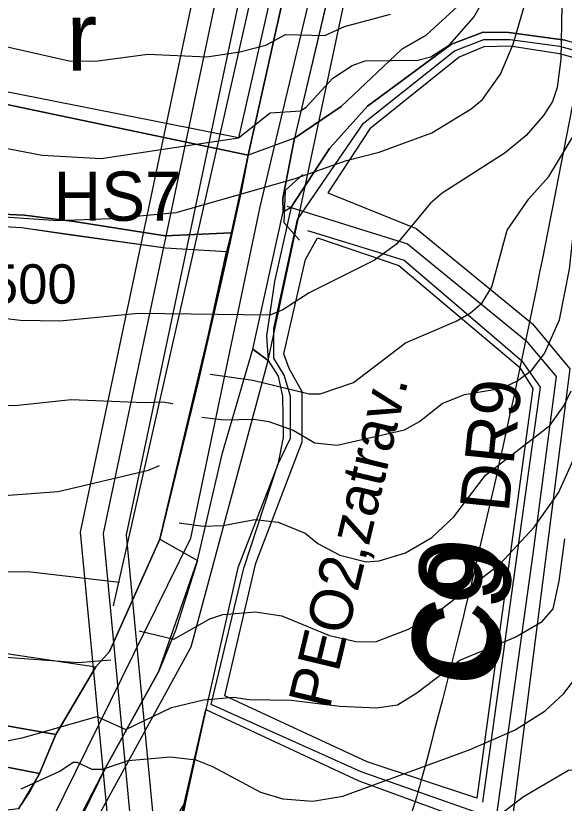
# Model space of a CAD drawing. Extents: x -684583 to -680383, y -1157874 to -1154904.
# Drawn here: x -683047.3 to -682880.2, y -1156898.5 to -1156658.6 of the extents above; entities that cross this region are included whole.
import ezdxf

# ---------------------------------------------------------------- set-up
doc = ezdxf.new("R2010")
doc.units = 0
for name, color, linetype in [('01_DOPRAVA', 7, 'Continuous'), ('01_OBVOD PÚ', 7, 'Continuous'), ('01_VRSTEVNICE', 7, 'Continuous'), ('02_KULTURY NÁVRH', 7, 'Continuous'), ('02_KULTURY STAV', 7, 'Continuous'), ('03_PC_NÁVRH', 7, 'Continuous'), ('03_PC_OBJEKTY_NÁVRH', 7, 'Continuous'), ('03_PC_OBJEKTY_STAV', 7, 'Continuous'), ('03_PC_POPIS_NÁVRH', 7, 'Continuous'), ('04_ZPF_OP_ORGAN', 7, 'Continuous'), ('06_BIOGEOGRAFIE', 7, 'Continuous'), ('06_ÚSES_IP', 7, 'Continuous'), ('07_ELEKTRO', 7, 'Continuous'), ('07_OCH_P A POPISY TI', 7, 'Continuous'), ('Implicitní', 7, 'Continuous')]:
    doc.layers.add(name, color=color, linetype=linetype)

msp = doc.modelspace()

# ---------------------------------------------------------------- linework, layer by layer
at = {"layer": '01_DOPRAVA'}
msp.add_lwpolyline([(-683054.51, -1157758.92), (-683045.66, -1157702.14), (-683033.32, -1157625.99), (-683033.32, -1157571.3), (-683045.07, -1157508.09), (-683105.62, -1157372.25), (-683148.82, -1157294.04), (-683163.81, -1157254.05), (-683168.81, -1157196.71), (-683165.28, -1157159.67), (-683135.89, -1157075.28), (-683079.46, -1156981.49), (-683035.96, -1156902.98), (-682993.94, -1156817.72), (-682972.78, -1156716.87), (-682952.5, -1156631.31), (-682921.05, -1156497.23), (-682883.43, -1156372.57), (-682870.79, -1156344.34), (-682802.61, -1156200.56), (-682782.62, -1156147.93)], dxfattribs=at)
at = {"layer": '01_OBVOD PÚ'}
for points in [[(-683140.88, -1156658.35), (-683073.72, -1156680.66), (-682976.5, -1156701.12), (-682978.52, -1156711.74), (-682983.61, -1156734.83), (-682991.74, -1156770.13), (-683003.34, -1156818.01)], [(-682976.5, -1156701.12), (-683073.72, -1156680.66), (-683140.88, -1156658.35)], [(-683046.43, -1156900.19), (-683042.88, -1156894.65), (-683040.05, -1156889.46), (-683036.16, -1156880.14), (-683035.02, -1156877.58), (-683022.83, -1156856.96), (-683018.7, -1156852.25), (-683003.34, -1156818.01), (-682983.61, -1156734.83), (-682976.5, -1156701.12)], [(-683003.34, -1156818.01), (-683018.7, -1156852.25), (-683022.83, -1156856.96), (-683035.02, -1156877.58), (-683036.16, -1156880.14), (-683040.05, -1156889.46), (-683042.88, -1156894.65), (-683045.48, -1156898.75)]]:
    msp.add_lwpolyline(points, dxfattribs=at)
for points in [[(-682989.36, -1156869.91), (-682942.73, -1156891.65), (-682905.01, -1156905.43), (-682910.21, -1156938.74), (-682911.04, -1156940.97), (-682922.78, -1156975.26), (-682939.17, -1157002.56), (-682940.26, -1157005.08), (-682945.41, -1157016.69), (-682955.51, -1157012.45), (-682965.71, -1157007.37), (-682974.58, -1157002.46), (-682979.82, -1156999.75), (-683040.73, -1156970.35), (-683038.56, -1156961.55), (-683037.65, -1156957.9), (-683028.68, -1156946.32), (-683018.91, -1156933.75), (-683016.64, -1156930.91), (-682996.6, -1156901.27), (-682995.5, -1156898)], [(-682989.36, -1156869.91), (-682942.73, -1156891.65), (-682905.01, -1156905.43), (-682910.21, -1156938.74), (-682922.78, -1156975.26), (-682939.17, -1157002.56), (-682945.41, -1157016.69), (-682955.51, -1157012.45), (-682965.71, -1157007.37), (-682974.58, -1157002.46), (-682979.82, -1156999.75), (-683040.73, -1156970.35), (-683037.34, -1156957.14), (-683028.68, -1156946.32), (-683018.91, -1156933.75), (-683016.64, -1156930.91), (-683005.44, -1156914.73), (-682996.6, -1156901.27)]]:
    msp.add_lwpolyline(points, close=True, dxfattribs=at)
at = {"layer": '01_VRSTEVNICE'}
for points in [[(-683179.87, -1156698.71), (-683173.88, -1156700.28), (-683165.89, -1156700.42), (-683139.93, -1156697.29), (-683127.95, -1156697.57), (-683113.97, -1156700.28), (-683097.99, -1156706.41), (-683087.15, -1156712.12), (-683076.31, -1156716.54), (-683058.34, -1156719.4), (-683034.37, -1156720.96), (-683018.4, -1156720.39), (-682998.42, -1156718.54), (-682962.48, -1156708.27), (-682946.5, -1156702.71), (-682936.52, -1156700.14), (-682920.54, -1156694.29), (-682908.56, -1156687.02), (-682905.13, -1156684.16), (-682899.57, -1156676.46), (-682895.72, -1156667.33), (-682888.45, -1156642.22)], [(-683174.02, -1156658.34), (-683167.6, -1156662.48), (-683153.34, -1156668.04), (-683141.35, -1156670.9), (-683125.38, -1156673.32), (-683111.4, -1156676.6), (-683096.85, -1156681.45), (-683080.59, -1156689.44), (-683062.04, -1156696.71), (-683039.22, -1156701.14), (-683021.25, -1156702.14), (-682979.45, -1156695.86), (-682969.75, -1156688.16), (-682960.48, -1156687.59), (-682958.77, -1156686.45), (-682950.64, -1156677.6), (-682944.79, -1156673.75), (-682940.8, -1156672.32), (-682924.82, -1156672.18), (-682920.83, -1156671.18), (-682915.12, -1156667.47), (-682907.7, -1156659.06), (-682901.28, -1156647.65)], [(-682990.58, -1156780.88), (-682983.88, -1156781.73), (-682974.75, -1156781.45), (-682970.18, -1156782.16), (-682962.76, -1156784.87), (-682956.2, -1156788.72), (-682949.36, -1156789.43), (-682928.82, -1156784.73), (-682924.25, -1156782.16), (-682917.4, -1156776.74), (-682910.56, -1156774.03), (-682899.15, -1156772.03), (-682894.58, -1156769.89), (-682890.01, -1156766.61), (-682886.16, -1156761.48), (-682881.6, -1156751.21), (-682878.6, -1156735.8), (-682877.46, -1156725.53), (-682875.47, -1156717.83), (-682866.05, -1156697.29), (-682855.92, -1156681.88), (-682849.93, -1156669.04), (-682844.51, -1156648.36)], [(-682988.01, -1156767.75), (-682975.03, -1156769.61), (-682957.91, -1156773.74), (-682954.49, -1156773.74), (-682944.36, -1156770.32), (-682928.53, -1156758.2), (-682913.12, -1156751.63), (-682908.7, -1156749.07), (-682905.14, -1156746.07), (-682902.28, -1156741.22), (-682897.58, -1156723.96), (-682891.01, -1156714.4), (-682884.88, -1156707.56), (-682874.04, -1156689.58), (-682869.33, -1156678.17), (-682865.62, -1156660.2), (-682859.2, -1156647.36)], [(-682880.89, -1156655.63), (-682881.17, -1156671.89), (-682882.31, -1156680.45), (-682883.74, -1156684.73), (-682886.45, -1156689.01), (-682891.73, -1156695.15), (-682898.15, -1156700.42), (-682917.4, -1156712.69), (-682920.97, -1156715.69), (-682931.24, -1156728.24), (-682937.94, -1156733.09), (-682957.91, -1156743.07), (-682965.9, -1156748.21), (-682969.9, -1156749.78), (-683009.84, -1156749.35), (-683033.8, -1156751.63), (-683045.78, -1156751.49), (-683053.77, -1156750.49)], [(-683123.1, -1156656.78), (-683109.12, -1156660.77), (-683101.13, -1156661.91), (-683083.16, -1156666.19), (-683078.88, -1156666.62), (-683072.88, -1156665.76), (-683058.91, -1156666.05), (-683030.95, -1156672.32), (-683022.96, -1156672.47), (-683006.98, -1156670.33), (-682989.01, -1156671.18), (-682979.03, -1156669.61), (-682971.04, -1156667.62), (-682965.05, -1156664.33), (-682953.06, -1156664.62), (-682947.07, -1156661.91), (-682933.09, -1156658.2)], [(-683183.58, -1156766.33), (-683154.76, -1156754.49), (-683150.48, -1156753.49), (-683141.92, -1156753.2), (-683117.67, -1156756.63), (-683104.84, -1156755.77), (-683096.28, -1156756.48), (-683087.72, -1156759.19), (-683082.73, -1156762.05), (-683066.89, -1156776.17), (-683061.19, -1156777.17), (-683047.49, -1156777.31), (-683030.38, -1156775.46), (-683008.12, -1156776.45), (-683002.42, -1156776.17), (-682999.42, -1156776.74)], [(-682997.43, -1156813.11), (-682990.15, -1156814.11), (-682984.16, -1156813.83), (-682974.43, -1156812.05), (-682967.33, -1156812.83), (-682959.05, -1156816.25), (-682955.2, -1156819.39), (-682948.5, -1156822.96), (-682940.51, -1156824.95), (-682936.52, -1156824.67), (-682928.53, -1156822.24), (-682920.54, -1156817.53), (-682913.84, -1156811.26), (-682904.14, -1156798.56), (-682884.59, -1156783.44), (-682880.32, -1156777.45), (-682878.03, -1156772.89)], [(-683009.69, -1156845.92), (-682999.14, -1156848.49), (-682988.11, -1156842.32), (-682984.2, -1156840.99), (-682974.18, -1156840.21), (-682966.19, -1156841.36), (-682951.64, -1156847.35), (-682943.65, -1156849.2), (-682937.66, -1156849.34), (-682927.67, -1156845.49), (-682919.97, -1156841.21), (-682899.71, -1156825.52), (-682889.3, -1156814.4), (-682881.88, -1156803.98), (-682870.62, -1156778.88)], [(-683181.86, -1156796.14), (-683150.48, -1156794.43), (-683134.79, -1156791.29), (-683117.67, -1156785.58), (-683110.54, -1156784.87), (-683103.41, -1156785.72), (-683099.13, -1156787.29), (-683093.43, -1156790.72), (-683084.3, -1156798.85), (-683078.59, -1156802.13), (-683064.33, -1156804.27), (-683052.34, -1156804.84), (-683034.37, -1156803.56), (-683006.84, -1156796.99), (-683003.42, -1156795.57)], [(-683187.57, -1156813.11), (-683149.63, -1156810.69), (-683131.65, -1156808.26), (-683115.68, -1156805.27), (-683107.55, -1156805.84), (-683102.55, -1156809.69), (-683089.43, -1156824.95), (-683086.86, -1156826.24), (-683078.59, -1156827.66), (-683042.65, -1156827.95), (-683015.68, -1156831.09)], [(-683057.76, -1156881.01), (-683044.93, -1156878.44), (-683022.53, -1156872.03), (-683013.69, -1156876.02), (-682999.85, -1156869.31), (-682990.08, -1156866.95), (-682980.82, -1156866.12), (-682976.17, -1156866.89), (-682963.33, -1156867.03), (-682948.5, -1156868.89), (-682937.37, -1156869.46), (-682930.95, -1156868.46), (-682925.11, -1156864.89), (-682911.98, -1156854.91), (-682895.15, -1156847.92), (-682886.88, -1156843.07), (-682883.6, -1156839.22), (-682881.74, -1156830.8), (-682880.03, -1156817.96)], [(-683257.75, -1156901.55), (-683256.33, -1156895.56), (-683255.9, -1156887.86), (-683257.32, -1156875.88), (-683256.61, -1156867.32), (-683253.9, -1156860.76), (-683249.05, -1156856.05), (-683242.63, -1156852.77), (-683222.09, -1156847.21), (-683209.11, -1156841.07), (-683199.84, -1156834.94), (-683191.28, -1156831.51), (-683186.14, -1156830.51), (-683175.87, -1156830.23), (-683151.34, -1156832.37), (-683124.24, -1156832.94), (-683119.96, -1156833.8), (-683112.83, -1156837.08), (-683097.13, -1156847.35), (-683076.31, -1156851.2), (-683055.77, -1156853.62), (-683028.24, -1156855.62), (-683018.25, -1156854.76)], [(-683045.64, -1156894.13), (-683033.8, -1156888.71), (-683029.81, -1156886), (-683028.67, -1156886), (-683024.1, -1156888.14), (-683020.68, -1156888.14), (-683012.97, -1156885.43), (-683000.14, -1156884.29), (-682992.43, -1156885.29), (-682987.3, -1156887.29), (-682972.75, -1156895.13), (-682965.9, -1156897.13), (-682956.77, -1156897.84), (-682947.64, -1156896.27), (-682908.84, -1156882.15), (-682895.15, -1156876.16), (-682886.02, -1156870.31), (-682880.32, -1156865.03), (-682871.76, -1156853.91)], [(-682910.56, -1156910.25), (-682892.58, -1156896.42), (-682878.89, -1156888.43), (-682873.75, -1156887.86), (-682870.47, -1156888.57), (-682868.62, -1156890.14), (-682866.62, -1156893.42), (-682865.91, -1156914.39)]]:
    msp.add_lwpolyline(points, dxfattribs=at)
at = {"layer": '02_KULTURY NÁVRH'}
msp.add_lwpolyline([(-682903.62, -1156902.45), (-682942.04, -1156888.88), (-682987.69, -1156868.38), (-682977.74, -1156826.92), (-682967.42, -1156795.29), (-682963.58, -1156787.26), (-682963.58, -1156774.45), (-682965.47, -1156768.08), (-682968.63, -1156762.95), (-682968.63, -1156753.87), (-682961.47, -1156720.7), (-682941.28, -1156691.3), (-682913.56, -1156669.28), (-682904.67, -1156665.82), (-682896.69, -1156665.82), (-682881.62, -1156667.93), (-682853.45, -1156675.62)], dxfattribs=at)
at = {"layer": '02_KULTURY STAV'}
for points in [[(-682976.5, -1156701.12), (-682962.69, -1156639.04), (-682954.15, -1156604.14), (-682942.64, -1156554.75), (-682933.67, -1156512.75), (-682930.39, -1156499.36), (-682924.11, -1156479.25), (-682902.2, -1156412.07), (-682889.47, -1156417.03), (-682900.44, -1156450.21), (-682906.88, -1156472.32), (-682918.22, -1156504.6), (-682924.52, -1156529.58), (-682939.75, -1156599.76), (-682949.64, -1156642.25), (-682962.33, -1156695.9)], [(-683111.36, -1156596.26), (-683052.03, -1156611.32), (-683020.92, -1156619.13), (-682998.1, -1156623.73), (-682980.21, -1156628.28), (-682966.28, -1156635.31), (-682962.69, -1156639.04), (-682976.5, -1156701.12), (-683073.72, -1156680.66), (-683140.88, -1156658.35), (-683138.49, -1156642.27), (-683137.49, -1156635.26), (-683133.3, -1156627.22), (-683127.66, -1156620.6)], [(-683003.34, -1156818.01), (-682991.86, -1156824.56), (-682984.3, -1156791.71), (-682974.99, -1156760.13), (-682965.76, -1156718.39), (-682965.87, -1156714.19), (-682962.33, -1156695.9), (-682976.5, -1156701.12), (-682978.52, -1156711.74), (-682983.61, -1156734.83), (-682991.74, -1156770.13)], [(-682965.76, -1156718.39), (-682963.36, -1156716.94), (-682968.45, -1156739.58), (-682970.92, -1156756.16), (-682970.35, -1156763.63), (-682974.99, -1156760.13)], [(-682983.03, -1156730.55), (-683001.65, -1156729.38), (-683030.45, -1156725.41), (-683045.5, -1156723.26), (-683057.74, -1156722.51), (-683065.56, -1156724.82), (-683070.42, -1156731.09), (-683078.9, -1156749.27), (-683089.07, -1156772.49), (-683108.63, -1156828.57), (-683108.54, -1156832.12), (-683084.67, -1156837.17), (-683086.85, -1156847.35), (-683022.84, -1156856.96), (-683018.7, -1156852.25), (-683003.34, -1156818.01), (-682991.74, -1156770.13)], [(-683056.67, -1156957.12), (-683048.23, -1156942.2), (-683019.85, -1156887.5), (-683003.71, -1156858.2), (-682991.86, -1156824.56), (-682984.3, -1156791.71), (-682974.99, -1156760.13), (-682970.35, -1156763.63), (-682967.31, -1156768.38), (-682966.01, -1156774.58), (-682965.79, -1156787.12), (-682967.42, -1156795.29), (-682979.58, -1156826.78), (-682989.36, -1156869.91), (-682995.5, -1156898), (-683016.64, -1156930.91), (-683028.68, -1156946.32), (-683037.65, -1156957.9), (-683040.73, -1156970.35)], [(-683086.85, -1156847.35), (-683022.84, -1156856.96), (-683035.02, -1156877.58), (-683070.73, -1156871.26), (-683070.45, -1156868.67), (-683069.49, -1156867.95), (-683068.52, -1156860.66), (-683079.75, -1156859.2)], [(-683131.89, -1156865.91), (-683104.59, -1156867.71), (-683070.73, -1156871.26), (-683035.02, -1156877.58), (-683040.05, -1156889.46), (-683070.37, -1156883.48), (-683118.26, -1156879.9), (-683137.12, -1156878.66), (-683137, -1156877.03)], [(-683118.26, -1156879.9), (-683070.37, -1156883.48), (-683040.05, -1156889.46), (-683046.43, -1156900.19), (-683055.25, -1156901.19), (-683100.37, -1156901.23), (-683122.59, -1156895.71), (-683134.37, -1156892.27), (-683135.43, -1156891.46), (-683119.29, -1156892.73)], [(-682995.5, -1156898), (-682996.97, -1156905.5), (-683000.81, -1156918.21), (-683004.43, -1156928.02), (-683005.16, -1156938.5), (-682980.59, -1156950.71), (-682937.18, -1156970.39), (-682930.27, -1156976.77), (-682916.7, -1156994.23), (-682937.14, -1157024.36), (-682955.51, -1157012.45), (-682951.84, -1157004.88), (-682951.52, -1156996.06), (-682967.04, -1156986.34), (-682968.47, -1156982.08), (-682970.56, -1156978.78), (-682980.18, -1156968.14), (-682974.44, -1156956.7), (-682993.49, -1156947.84), (-682999.31, -1156957.41), (-683028.68, -1156946.32), (-683016.64, -1156930.91), (-682996.6, -1156901.27)]]:
    msp.add_lwpolyline(points, close=True, dxfattribs=at)
for points in [[(-682939.75, -1156599.76), (-682962.33, -1156695.9), (-682948.11, -1156686.24), (-682929.63, -1156668.82), (-682922.2, -1156664.52), (-682911.39, -1156654.62)], [(-682911.39, -1156654.62), (-682922.2, -1156664.52), (-682929.63, -1156668.82), (-682948.11, -1156686.24), (-682962.33, -1156695.9), (-682965.87, -1156714.19), (-682965.76, -1156718.39), (-682963.36, -1156716.94), (-682951.69, -1156699.11), (-682940.09, -1156686.12), (-682914.52, -1156667.28), (-682904.87, -1156663.67), (-682897.05, -1156663.74), (-682879.93, -1156666.03), (-682851.53, -1156673.88), (-682832.12, -1156679.28), (-682832.61, -1156655.83)], [(-683140.88, -1156658.35), (-683073.72, -1156680.66), (-682976.5, -1156701.12), (-682981.6, -1156724.74), (-683001.73, -1156725.68), (-683029.44, -1156721.32), (-683044.74, -1156719.4), (-683057.97, -1156718.78), (-683067.44, -1156721.96), (-683073.73, -1156729.62), (-683082.27, -1156747.67), (-683096.38, -1156780.58), (-683097.13, -1156784.04), (-683102.02, -1156784.54), (-683114.59, -1156783.64), (-683123.92, -1156781.39), (-683136.63, -1156773.5), (-683150.31, -1156762.56), (-683175.1, -1156745.81)], [(-682879.93, -1156666.03), (-682897.05, -1156663.74), (-682904.87, -1156663.67), (-682914.52, -1156667.28), (-682940.09, -1156686.12), (-682951.69, -1156699.11), (-682963.36, -1156716.94), (-682968.45, -1156739.58), (-682970.92, -1156756.16), (-682970.35, -1156763.63), (-682967.31, -1156768.38), (-682966.01, -1156774.58), (-682965.79, -1156787.12), (-682967.42, -1156795.29), (-682979.58, -1156826.78), (-682989.36, -1156869.91), (-682995.5, -1156898), (-682996.97, -1156905.5)], [(-683057.97, -1156718.78), (-683044.74, -1156719.4), (-683029.44, -1156721.32), (-683001.73, -1156725.68), (-682981.6, -1156724.74), (-682983.03, -1156730.55), (-683001.65, -1156729.38), (-683045.5, -1156723.26), (-683057.74, -1156722.51)], [(-683046.43, -1156900.19), (-683042.88, -1156894.65), (-683040.05, -1156889.46), (-683035.02, -1156877.58), (-683022.83, -1156856.96), (-683018.7, -1156852.25), (-683003.34, -1156818.01), (-682991.86, -1156824.56), (-682998.6, -1156845.85), (-683003.71, -1156858.2), (-683019.85, -1156887.5), (-683036.61, -1156921.65)]]:
    msp.add_lwpolyline(points, dxfattribs=at)
at = {"layer": '03_PC_NÁVRH'}
msp.add_lwpolyline([(-682964.69, -1156716.62), (-682927.89, -1156728.11), (-682891.83, -1156757.49), (-682882.59, -1156768.47), (-682889.7, -1156822.56), (-682904.3, -1156926.72), (-682913.8, -1156959.84)], dxfattribs=at)
at = {"layer": '03_PC_OBJEKTY_NÁVRH'}
msp.add_lwpolyline([(-682958.38, -1156723.99), (-682928.92, -1156733.08), (-682893.19, -1156763.6), (-682887.49, -1156771.76), (-682905.05, -1156898.13)], dxfattribs=at)
at = {"layer": '03_PC_OBJEKTY_STAV'}
msp.add_lwpolyline([(-682960.78, -1156726.94), (-682965.54, -1156721.71), (-682965.07, -1156711.72), (-682959.84, -1156706.96)], dxfattribs=at)
at = {"layer": '04_ZPF_OP_ORGAN'}
for points in [[(-683109.63, -1156601.48), (-682983.62, -1156631.85), (-682967.02, -1156641.18), (-682979.45, -1156695.86), (-683071.68, -1156677.56), (-683136.35, -1156655.1), (-683133.94, -1156635.23)], [(-682955.35, -1156726.28), (-682930.61, -1156734.72), (-682893.79, -1156765.65), (-682889.77, -1156772.2), (-682906.8, -1156896.92), (-682940.21, -1156885.83), (-682983.58, -1156865.74), (-682974.1, -1156825.4), (-682959.97, -1156788.44), (-682959.97, -1156773.17), (-682963.98, -1156766.1), (-682965.59, -1156761.6), (-682959.01, -1156732.83)]]:
    msp.add_lwpolyline(points, close=True, dxfattribs=at)
msp.add_lwpolyline([(-682894.88, -1156964.91), (-682864.52, -1156891.82), (-682859.24, -1156872.77), (-682855.92, -1156847.92), (-682855.92, -1156827.46), (-682860.58, -1156813.95), (-682860.58, -1156793.05), (-682857.73, -1156777.95), (-682860.41, -1156744.38), (-682860.41, -1156711.74), (-682855.63, -1156677.25), (-682881.62, -1156670.21), (-682896.69, -1156667.86), (-682904.67, -1156668.11), (-682912.16, -1156671.21), (-682939.42, -1156693.11), (-682952.17, -1156712.58), (-682925.24, -1156723.41), (-682889.85, -1156752.44), (-682878.44, -1156766.12), (-682899.08, -1156927.48)], dxfattribs=at)
at = {"layer": '06_BIOGEOGRAFIE'}
for points in [[(-682624.87, -1154935.44), (-682669.05, -1155140.04), (-682739.65, -1155253.72), (-682834.36, -1155382.91), (-682941.12, -1155661.96), (-683008.28, -1155760.14), (-683056.49, -1155810.09), (-683084.04, -1155808.37), (-683154.45, -1155886.49), (-683231.94, -1156062.19), (-683280.08, -1156211.64), (-683362.74, -1156430.39), (-683497.05, -1156731.83), (-683541.82, -1156781.78), (-683638.25, -1156792.12), (-683701.96, -1156768), (-683817.33, -1156693.94)], [(-682820.52, -1156443.86), (-682794.69, -1156436.97), (-682777.47, -1156454.19), (-682792.96, -1156667.78), (-682801.57, -1156726.35), (-682792.96, -1156755.63), (-682811.91, -1156802.14), (-682839.46, -1156886.54), (-682887.67, -1157000.23), (-682920.39, -1157038.12)], [(-683099.47, -1156889.99), (-683108.08, -1156852.09), (-683133.91, -1156841.76), (-683133.91, -1156814.2), (-683132.19, -1156784.91), (-683147.69, -1156747.02), (-683189.01, -1156748.74), (-683242.39, -1156712.57), (-683235.51, -1156631.61), (-683171.79, -1156531.71), (-683097.75, -1156511.04), (-683004.76, -1156526.54), (-682887.67, -1156483.48), (-682868.73, -1156459.36), (-682823.96, -1156452.47), (-682839.46, -1156516.2), (-682863.56, -1156605.77), (-682887.67, -1156736.68), (-682923.83, -1156891.71), (-682934.16, -1156915.82), (-682965.16, -1156929.6), (-683004.76, -1156926.16)], [(-683605.53, -1156693.94), (-683552.15, -1156773.17), (-683505.66, -1156862.74), (-683385.12, -1156876.52), (-683240.48, -1156867.91), (-682983.91, -1156935.09), (-682923.69, -1156998.38), (-682921.97, -1157094.84), (-682923.69, -1157198.19), (-682892.7, -1157272.26), (-682746.33, -1157329.1), (-682572.41, -1157337.72), (-682417.44, -1157289.49), (-682386.73, -1157266.62)], [(-683662.04, -1156787.77), (-683658.6, -1156877.34), (-683631.05, -1156927.29), (-683541.5, -1156975.52), (-683489.85, -1157028.92), (-683414.08, -1157027.2), (-683362.42, -1157025.48), (-683360.7, -1157063.37), (-683464.02, -1157132.27), (-683493.29, -1157163.28), (-683474.35, -1157189.11), (-683407.19, -1157171.89), (-683317.65, -1157115.05), (-683269.44, -1157104.71), (-683207.44, -1157173.61), (-683186.78, -1157259.74), (-683105.85, -1157416.48), (-683069.69, -1157530.17), (-683073.13, -1157580.12), (-683097.24, -1157628.35), (-683264.27, -1157657.63), (-683431.3, -1157647.3), (-683531.17, -1157605.96), (-683636.21, -1157542.23), (-683651.71, -1157521.56), (-683682.7, -1157519.83), (-683708.53, -1157528.45), (-683818.74, -1157547.39), (-683870.4, -1157518.11), (-683980.6, -1157521.56), (-684052.92, -1157490.55), (-684171.74, -1157400.98), (-684213.07, -1157375.14), (-684250.95, -1157388.92), (-684249.23, -1157437.15), (-684237.17, -1157466.44), (-684170.02, -1157518.11), (-684097.7, -1157562.9), (-684011.6, -1157605.96), (-683953.05, -1157602.51), (-683891.06, -1157626.63), (-683835.96, -1157619.74), (-683789.47, -1157599.07), (-683713.7, -1157578.4), (-683625.88, -1157592.18), (-683551.84, -1157667.97), (-683445.07, -1157736.87), (-683346.92, -1157771.32), (-683179.89, -1157767.87), (-683081.74, -1157773.04), (-683016.71, -1157810.65), (-682999.16, -1157844)]]:
    msp.add_spline(points, degree=3, dxfattribs=at)
at = {"layer": '06_ÚSES_IP'}
for points in [[(-682530.18, -1155187.74), (-682556.31, -1155287.32), (-682580.65, -1155417.4), (-682596.62, -1155505.37), (-682619.02, -1155596.96), (-682637.3, -1155662.36), (-682672.55, -1155772.07), (-682712.43, -1155905.02), (-682772.45, -1156078.06), (-682846.1, -1156262.2), (-682899.06, -1156383.28), (-682928.82, -1156472.07), (-682968.71, -1156622.54), (-683017.6, -1156838.34)], [(-683045.5, -1156945.1), (-682993.87, -1156850.83), (-682970.35, -1156763.63), (-682943.14, -1156635.49), (-682907.69, -1156485.87), (-682877.43, -1156403.71), (-682855.81, -1156343.74), (-682797.01, -1156219.49), (-682773.09, -1156158.67), (-682722.07, -1156008.47), (-682663.84, -1155833.77), (-682598.99, -1155629.09), (-682554.6, -1155429.31), (-682533.56, -1155299)]]:
    msp.add_lwpolyline(points, dxfattribs=at)
at = {"layer": '07_ELEKTRO'}
msp.add_lwpolyline([(-683353.35, -1157770.3), (-683109.07, -1157109.08), (-683073.5, -1157019.42), (-683054.68, -1156978.22), (-683011.49, -1156911.63), (-683020.57, -1156816.29), (-682818.44, -1155857.57), (-682314.17, -1155533.82)], dxfattribs=at)
msp.add_lwpolyline([(-683353.35, -1157770.3), (-683109.07, -1157109.08), (-683073.5, -1157019.42), (-683054.68, -1156978.22), (-683011.49, -1156911.63), (-683020.57, -1156816.29), (-682818.44, -1155857.57), (-682314.17, -1155533.82)], dxfattribs=at)
at = {"layer": '07_OCH_P A POPISY TI'}
for p, q in [((-683013.5, -1156816.69), (-682812.19, -1155861.88)), ((-682826.85, -1155863.53), (-683027.64, -1156815.89)), ((-683027.64, -1156815.89), (-683018.69, -1156909.87)), ((-683004.29, -1156913.39), (-683013.5, -1156816.69))]:
    msp.add_line(p, q, dxfattribs=at)

# ---------------------------------------------------------------- texts
at = {"layer": '01_VRSTEVNICE'}
msp.add_text('500', height=12, dxfattribs=at).set_placement((-683055.46, -1156746.32))
at = {"layer": '02_KULTURY STAV'}
msp.add_text('r', height=21, dxfattribs=at).set_placement((-683031.8, -1156675.34))
at = {"layer": '03_PC_OBJEKTY_NÁVRH'}
msp.add_text('DR9', height=15, rotation=84.2134, dxfattribs=at).set_placement((-682897.12, -1156810.15))
at = {"layer": '03_PC_OBJEKTY_STAV'}
msp.add_text('HS7', height=15, dxfattribs=at).set_placement((-683035.73, -1156721.07))
at = {"layer": '03_PC_POPIS_NÁVRH'}
msp.add_text('C9', height=25, rotation=81.3303, dxfattribs=at).set_placement((-682901.6, -1156864.27))
at = {"layer": '04_ZPF_OP_ORGAN'}
msp.add_text('PEO2,zatrav.', height=13, rotation=76.5332, dxfattribs=at).set_placement((-682951.69, -1156870.17))
at = {"layer": 'Implicitní'}
msp.add_text('C9', height=25, rotation=84.1513, dxfattribs=at).set_placement((-682902.78, -1156861.66))

doc.saveas('drawing.dxf')
